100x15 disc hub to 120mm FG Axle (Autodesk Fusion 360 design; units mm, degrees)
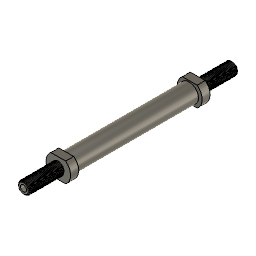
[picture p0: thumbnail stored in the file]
sketch "Sketch1" plane through (0, 0, 0) normal (0, 1, 0) x axis (1, 0, 0)
  circle C1 centre (0, 0) radius 7.475
  point P1 (0, 0)
  point P2 (0, 0)
  coincident P1 P2
  dimension "d1" diameter C1 = 14.95
extrude "Extrude1" new body sketch "Sketch1" distance 49.5
sketch "Sketch2" plane through (0, -49.5, 0) normal (0, -1, 0) x axis (1, 0, 0)
  line L1 (-7, 8) -> (7, 8)
  line L2 (7, -8) -> (-7, -8)
  circle C1 centre (0, 0) radius 7.475
  circle C2 centre (0, 0) radius 10
  point P1 (0, 0)
  point P3 (0, 0)
  coincident P1 P3
  horizontal L1
  horizontal L2
  dimension "d4" diameter C2 = 20
extrude "Extrude2" add sketch "Sketch2" along normal blind 6.5
sketch "Sketch3" plane through (0, -56, 0) normal (0, -1, 0) x axis (1, 0, 0)
  line L1 (6, -8) -> (-6, -8)
  line L2 (-6, 8) -> (6, 8)
  circle C1 centre (0, 0) radius 5
  arc A1 centre (0, 0) radius 10 clockwise from (-6, -8) to (-6, 8)
  arc A2 centre (0, 0) radius 10 clockwise from (6, 8) to (6, -8)
  point P1 (0, 0)
  point P2 (0, 0)
  coincident P1 P2
  dimension "d7" diameter C1 = 10
extrude "Extrude3" add sketch "Sketch3" profile of C1 along normal blind 28
thread "Thread1" ThreadOffset 0 ThreadLength 10
chamfer "Chamfer2" distance 1
sketch "Sketch4" plane through (0, 49.5, 0) normal (0, 1, 0) x axis (-1, 0, 0)
  circle C1 centre (0, 0) radius 7.475
  circle C2 centre (0, 0) radius 6
  concentric C1 C2
sketch "Sketch5" plane through (0, 49.5, 0) normal (0, 1, 0) x axis (-1, 0, 0)
  line L1 (7, 8) -> (-7, 8)
  line L2 (7, -8) -> (-7, -8)
  circle C1 centre (0, 0) radius 7.475
  circle C2 centre (0, 0) radius 10
  point P1 (0, 0)
  point P3 (0, 0)
  coincident P1 P3
  horizontal L1
  horizontal L2
extrude "Extrude5" new body sketch "Sketch5" along normal blind 6.5
sketch "Sketch6" plane through (0, 56, 0) normal (0, 1, 0) x axis (-1, 0, 0)
  line L1 (6, -8) -> (-6, -8)
  line L2 (-6, 8) -> (6, 8)
  arc A1 centre (0, 0) radius 10 clockwise from (-6, -8) to (-6, 8)
  arc A2 centre (0, 0) radius 10 clockwise from (6, 8) to (6, -8)
  circle C1 centre (0, 0) radius 5
  point P1 (0, 0)
  point P7 (0, 0)
  coincident P1 P7
  dimension "d16" diameter C1 = 10
extrude "Extrude6" add sketch "Sketch6" profile of C1 along normal blind 28
thread "Thread2" ThreadOffset 0 ThreadLength 10
chamfer "Chamfer1" distance 1
sketch "Sketch7" plane through (0, 49.5, 0) normal (0, -1, 0) x axis (1, 0, 0)
  line L1 (-6, 8) -> (6, 8)
  line L2 (6, -8) -> (-6, -8)
  arc A1 centre (0, 0) radius 10 clockwise from (6, 8) to (6, -8)
  arc A2 centre (0, 0) radius 10 clockwise from (-6, -8) to (-6, 8)
  circle C1 centre (0, 0) radius 6
  point P1 (0, 0)
  point P7 (0, 0)
  coincident P1 P7
  dimension "d21" diameter C1 = 12
extrude "Extrude7" add sketch "Sketch7" profile of C1 along normal blind 15
thread "Thread3" ThreadOffset 0 ThreadLength 10
hole "Hole1" HoleDepth 100 HoleDiameter 10.274 TipAngle 180
fillet "Fillet1" radius 5
move "Move1"
sketch "Sketch8" plane through (0, -84, 0) normal (0, -1, 0) x axis (1, 0, 0)
  circle C1 centre (0, 0) radius 2.5
  circle C2 centre (0, 0) radius 3.942
  point P1 (0, 0)
  point P2 (0, 0)
  coincident P1 P2
extrude "Extrude8" cut sketch "Sketch8" profile of C1 against normal blind 180
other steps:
thread "Thread4" ThreadOffset 0 ThreadDepth 15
